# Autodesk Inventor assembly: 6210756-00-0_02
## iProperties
Category: PARTsolutions
Created: 2011-08
Part Number: 6210756-00-0_02
Catalog Web Link: www.cadenas.de
Description: S SX 1250 - Stahlketten
Document SubType Name: Assembly
Designer: PARTsolutions
NB: S 1250-242 (5125,380,7100,0,0622)
NN: S SX 1250
NT: Stahlketten
NBSYN: S 1250-242 (5125,380,7100,0,0622)
LINA: S 1250.242-380-5125 FAI/MAI
PSOL_MULTISOLIDPART: 0.0
TYP: S 1250
BI: 242
BK: 291
BST: 267
LK: 5125
KR: 380
LS: 7100
LV: 0
STEGV: 6
FA: 2
MA: 2
LF: 3737.500
ESP: 0
PSTOL: 0.010
T: 125.000
LS2: 3550.000
DR: 81.195
LB: 1568.805
EASS: 0.000
VAR: 1.000
LKA: 5250.000
MOD1: 0.000
RX2: 760.000
HI: 69
HG: 94
TYP1: S1250
BIMIN: 101.000
BIMAX: 751.000
KRV: 145,200,220,260,300,340,380,420,460,500,540,600,700
LSMAX: 150000.000
BKMIN: 150.000
BKMAX: 800.000
INFO: PDF Katalog
PPATH: assemblies/1250_asmtpl.prj
FABEST: FAI
MABEST: MAI
KT: DUMMY
CreationOption_UseAsmMates: 0
SUPPLIER: Kabelschlepp
ARTICLENO: S 1250-242 (5125,380,7100,0,0622)
BOMINFO: S 1250.242-380-5125 FAI/MAI
CREATOR: CADENAS GmbH
PSOL_IDENT_0: {\\10.0.0.251\ps_data\23d-libs\kabelschlepp\4_eketten_st\s_sx_1250_asmtab.prj},237 {VTYP=3D},{STYP=A
PSOL_IDENT_1: SSTAB},{NB=S 1250-242 (5125,380,7100,0,0622)},{LINA=S 1250.242-380-5125 FAI/MAI},{NN=S SX 1250},{DAT
PSOL_IDENT_2: E=14.01.2010 07:21:25},{GEOMDATE=17.03.2008},{VERSION=},{LINEID=10},{LINESUBID=-1},{WBVAR=BI,KR,LS,L
PSOL_IDENT_3: V,STEGV,FA,MA,ESP}  {NB=S 1250-242 (5125,380,7100,0,0622)},{LINA=S 1250.242-380-5125 FAI/MAI},{KT=DU
PSOL_IDENT_4: MMY},{TYP=S 1250},{BI=242},{BK=291},{BST=267},{LK=5125},{KR=380},{LS=7100},{LV=0},{STEGV=6},{FA=2},{
PSOL_IDENT_5: MA=2},{LF=3737.5},{ESP=0},{PSTOL=0.010},{T=125.000},{LS2=3550},{DR=81.194792},{LB=1568.805208},{EASS
PSOL_IDENT_6: =0},{VAR=1},{LKA=5250},{MOD1=0},{RX2=760},{NB1=},{HI=69},{HG=94},{TYP1=S1250},{BIMIN=101},{BIMAX=751
PSOL_IDENT_7: },{KRV=145,200,220,260,300,340,380,420,460,500,540,600,700},{LSMAX=150000.000},{SV=-1000000015047466
PSOL_IDENT_8: 200000000000000.00},{SV1=},{BKMIN=150},{BKMAX=800},{INFO=PDF Katalog},{PPATH=assemblies/1250_asmtpl.
PSOL_IDENT_9: prj},{FABEST=FAI},{MABEST=MAI}
Title: S 1250.242-380-5125 FAI/MAI
Author: Cadenas PARTsolutions
Comments: Stahlketten
